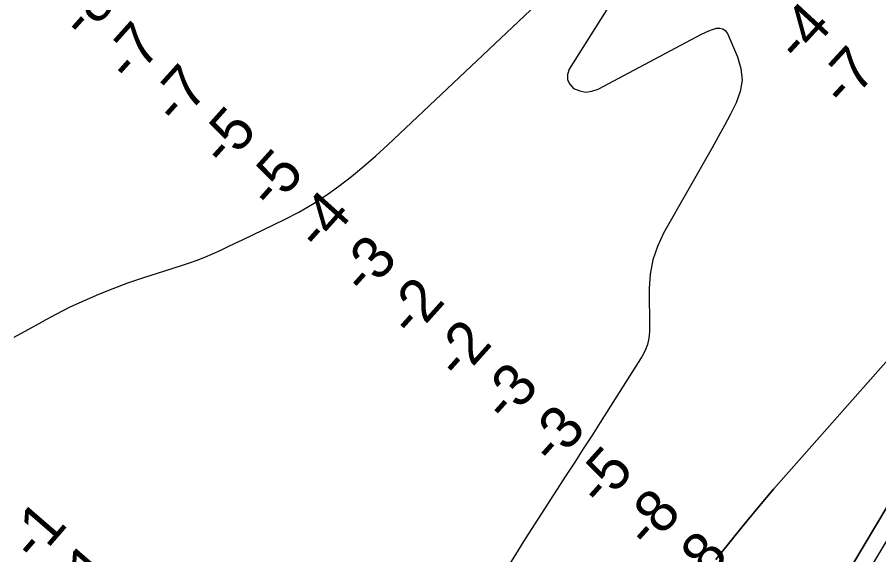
# Model space of a CAD drawing. Extents: x 3324104 to 3361979, y 612876 to 638273.
# Drawn here: x 3338795 to 3340154, y 623340 to 624187 of the extents above; entities that cross this region are included whole.
import ezdxf

# ---------------------------------------------------------------- set-up
doc = ezdxf.new("R2010")
doc.units = 0
for name, color, linetype in [('V-RIVR-EDGE', 7, 'Continuous'), ('V-RIVR-RANG', 7, 'Continuous'), ('V-TOPO-DPTH', 7, 'Continuous'), ('V-TOPO-MINR', 7, 'Continuous')]:
    doc.layers.add(name, color=color, linetype=linetype)

msp = doc.modelspace()

# ---------------------------------------------------------------- linework, layer by layer
at = {"layer": 'V-RIVR-EDGE'}
msp.add_spline([(3338849.5, 620833.7), (3338863.9, 620858.4), (3338873.2, 620877), (3338879.5, 620892.9), (3338887.7, 620911.1), (3338889.2, 620920.8), (3338889.3, 620930.9), (3338889.3, 620936.7), (3338892.8, 620944.8), (3338909.2, 620979.3), (3338928.6, 621017.7), (3338934.9, 621032.8), (3338933, 621036.3), (3338935.3, 621042.1), (3338955.2, 621075.8), (3338956.3, 621080), (3338951.3, 621082.4), (3338952.5, 621087.4), (3338954, 621094.8), (3338957.5, 621099.4), (3338963, 621104.8), (3338961.4, 621110.7), (3338960.7, 621117.6), (3338962.2, 621121.5), (3338980.9, 621151.3), (3338987.5, 621160.2), (3338994.6, 621173), (3339001.6, 621180.4), (3339008.6, 621185.8), (3339012.8, 621191.6), (3339013.6, 621197), (3339013.2, 621200.9), (3339009.8, 621206.7), (3339008.2, 621211.8), (3339009, 621213.7), (3339012.5, 621216.8), (3339014.8, 621221.1), (3339014.9, 621226.5), (3339018.4, 621227.2), (3339028, 621227.6), (3339031.2, 621232.3), (3339035.1, 621243.9), (3339039.8, 621256.3), (3339042.9, 621268.7), (3339045.6, 621270.2), (3339049.9, 621273.7), (3339052.6, 621276.8), (3339055.3, 621283.8), (3339058.5, 621297.7), (3339063.5, 621308.2), (3339066.3, 621319), (3339072.9, 621338), (3339074.5, 621340.7), (3339071.8, 621346.2), (3339071.4, 621350.8), (3339070.6, 621355.9), (3339070.6, 621360.9), (3339074.6, 621374.9), (3339080, 621383.4), (3339091.3, 621402), (3339101.8, 621418.6), (3339106.9, 621432.2), (3339108.9, 621448.5), (3339114.7, 621460.9), (3339121.7, 621472.9), (3339138.1, 621494.5), (3339146.6, 621512.7), (3339150.9, 621515.8), (3339154, 621517), (3339157.5, 621520.5), (3339162.2, 621524.7), (3339162.6, 621530.9), (3339163, 621535.2), (3339166.5, 621539.4), (3339173.9, 621548.4), (3339187.9, 621560), (3339202.3, 621575.4), (3339208.5, 621582), (3339220.9, 621601.4), (3339227.2, 621611.8), (3339228.3, 621618.4), (3339232.6, 621620.7), (3339234.6, 621627.7), (3339234.6, 621632.4), (3339233.8, 621643.2), (3339233.9, 621652.9), (3339235, 621660.7), (3339237.8, 621668.8), (3339245.6, 621681.6), (3339256.4, 621692), (3339259.6, 621702.1), (3339260.4, 621709.5), (3339267.8, 621721.9), (3339275.9, 621735.4), (3339287.3, 621761), (3339293.1, 621772.6), (3339304, 621793.5), (3339318, 621822.9), (3339329.7, 621836.9), (3339335.2, 621843.1), (3339330.5, 621848.9), (3339330.5, 621851.6), (3339333.3, 621855.9), (3339336.4, 621859.7), (3339342.2, 621865.5), (3339347.6, 621869.8), (3339357, 621888), (3339376.1, 621923.6), (3339382.7, 621941.8), (3339386.6, 621950.8), (3339393.2, 621962.8), (3339404.5, 621981.7), (3339427.1, 622013.9), (3339446.2, 622044.5), (3339464.1, 622073.5), (3339479.3, 622102.9), (3339498.8, 622140.9), (3339514.4, 622174.6), (3339531.9, 622205.2), (3339537.7, 622216), (3339537.7, 622219.9), (3339534.7, 622225.7), (3339534.7, 622228.8), (3339534.7, 622231.9), (3339539.7, 622235), (3339547.5, 622242.8), (3339556.8, 622254), (3339556.8, 622259.8), (3339555.7, 622266.4), (3339558.4, 622271.4), (3339563.9, 622273.7), (3339568.6, 622287.7), (3339574, 622293.9), (3339576.3, 622298.5), (3339576.4, 622305.1), (3339577.9, 622309.8), (3339583.4, 622315.6), (3339592.7, 622321.8), (3339605.1, 622339.6), (3339611, 622347.3), (3339621.1, 622355.4), (3339623.8, 622361.6), (3339624.2, 622367.4), (3339624.6, 622374.8), (3339628.1, 622381.4), (3339634.7, 622394.2), (3339652.6, 622417.8), (3339667, 622436.8), (3339680.3, 622456.9), (3339694.3, 622479), (3339705.2, 622499.1), (3339708.7, 622510.7), (3339714.6, 622523.5), (3339723.1, 622538.6), (3339729.4, 622550.2), (3339737.9, 622567.3), (3339738.7, 622571.9), (3339742.2, 622573.5), (3339746.9, 622573.8), (3339748.4, 622577.7), (3339749.2, 622585.1), (3339752, 622591.3), (3339757.8, 622596.7), (3339769.1, 622612.6), (3339778.4, 622620.3), (3339791.2, 622628), (3339795.5, 622636.5), (3339804.1, 622654), (3339820.4, 622682.2), (3339834.5, 622707.8), (3339891.3, 622796.9), (3339910, 622829.4), (3339944.6, 622882.4), (3339978.1, 622936.2), (3339998.7, 622964.9), (3340017.1, 622997.8), (3340021, 623017.2), (3340025.7, 623025.3), (3340038.9, 623040.4), (3340052.9, 623059.4), (3340070.8, 623091.9), (3340085.6, 623112.8), (3340108.6, 623149.2), (3340144.4, 623201.5), (3340174, 623254.2), (3340198.1, 623280.1), (3340221.4, 623307.2), (3340237, 623327.3), (3340244.4, 623342), (3340256.8, 623363.3), (3340272.8, 623384.6), (3340289.1, 623408.2), (3340302.8, 623428.7), (3340311.7, 623438.8), (3340319.5, 623450.4), (3340319.5, 623457.8), (3340325, 623465.9), (3340333.5, 623476.7), (3340341.3, 623483.3), (3340352.2, 623496.5), (3340367.4, 623520.1), (3340394.2, 623560), (3340400.1, 623574.3), (3340403.2, 623588.6), (3340409.1, 623600.7), (3340420.7, 623609.9), (3340437, 623624.6), (3340446.4, 623639.7), (3340451.1, 623650.6), (3340458.1, 623662.2), (3340477.1, 623683.9), (3340488, 623697)], degree=3, dxfattribs=at)
at = {"layer": 'V-TOPO-DPTH'}
for points in [[(3339896.4, 623332.9), (3339903.2, 623341.2), (3339938.3, 623384.4), (3339962.8, 623414.2), (3339987.5, 623443.7), (3340345.6, 623847.9), (3340365.7, 623866.5), (3340387.4, 623883.3), (3340410, 623898.9), (3340464.3, 623932.8), (3340471.7, 623933.2), (3340476.9, 623931.4), (3340478.7, 623926.3), (3340478.3, 623918.9), (3340474.1, 623912.1), (3340464.4, 623897), (3340454.5, 623882.1), (3340444.2, 623867.4), (3340433.7, 623852.9), (3340423, 623838.5), (3340412.3, 623824), (3340401.8, 623809.5), (3340077.1, 623265.5)], [(3340077.1, 623265.5), (3340401.8, 623809.5), (3340412.3, 623824), (3340423, 623838.5), (3340433.7, 623852.9), (3340444.2, 623867.4), (3340454.5, 623882.1), (3340464.4, 623897), (3340474.1, 623912.1), (3340478.3, 623918.9), (3340478.7, 623926.3), (3340476.9, 623931.4), (3340471.7, 623933.2), (3340464.3, 623932.8), (3340410, 623898.9), (3340387.4, 623883.3), (3340365.7, 623866.5), (3340345.6, 623847.9), (3339987.5, 623443.7), (3339962.8, 623414.2), (3339938.3, 623384.4), (3339903.2, 623341.2), (3339896.4, 623332.9)]]:
    msp.add_lwpolyline(points, dxfattribs=at)
at = {"layer": 'V-TOPO-MINR'}
for points in [[(3338789.5, 623683), (3338811.6, 623695.1), (3338833.6, 623707.4), (3338834.3, 623707.8), (3338856.1, 623719.6), (3338878, 623730.7), (3338900.4, 623741.1), (3338923.1, 623750.9), (3338946.1, 623759.9), (3338969.2, 623768.6), (3338992.5, 623776.6), (3339016, 623784.2), (3339053.8, 623796), (3339066.2, 623800.1), (3339078.5, 623804.5), (3339090.6, 623809.4), (3339102.6, 623814.5), (3339114.5, 623820), (3339126.4, 623825.5), (3339138.2, 623831.1), (3339150, 623836.7), (3339216.3, 623868.7), (3339238.6, 623880.3), (3339260.5, 623892.7), (3339281.5, 623906.5), (3339302, 623921.1), (3339321.9, 623936.6), (3339341.4, 623952.6), (3339360.4, 623969.1), (3339379, 623986.1), (3339791.6, 624375.5)], [(3339820, 624350.9), (3339665.2, 624105.6), (3339662.5, 624097), (3339662.3, 624088.9), (3339666, 624081.7), (3339672.2, 624075.2), (3339681.8, 624071.3), (3339691.4, 624069.4), (3339701.1, 624070.7), (3339710.8, 624074), (3339874.1, 624160.8), (3339879.7, 624163.6), (3339885.5, 624166.1), (3339891.4, 624168.3), (3339897.4, 624170.2), (3339902.8, 624170.4), (3339907.6, 624169.3), (3339911.5, 624166.3), (3339914.7, 624162), (3339930.9, 624124.8), (3339936.1, 624106.5), (3339938, 624088.3), (3339935, 624070.2), (3339928.7, 624052.3), (3339919.5, 624034.4), (3339910, 624016.7), (3339900.4, 623999.1), (3339890.6, 623981.6), (3339814.1, 623847), (3339804.4, 623826.2), (3339797, 623804.8), (3339793, 623782.5), (3339791.4, 623759.6), (3339791.6, 623733.8), (3339791.7, 623723.3), (3339791.7, 623712.8), (3339791.7, 623702.3), (3339791.7, 623691.8), (3339790.8, 623681.6), (3339788.8, 623671.7), (3339785.1, 623662.2), (3339780.4, 623653.1), (3339713.9, 623548.4), (3339700.7, 623527.6), (3339687.4, 623506.9), (3339674.1, 623486.2), (3339660.7, 623465.5), (3339595.7, 623365.4), (3339559.9, 623307.4)], [(3340077.1, 623265.5), (3340401.8, 623809.5), (3340412.3, 623824), (3340423, 623838.5), (3340433.7, 623852.9), (3340444.2, 623867.4), (3340454.5, 623882.1), (3340464.4, 623897), (3340474.1, 623912.1), (3340478.3, 623918.9), (3340478.7, 623926.3), (3340476.9, 623931.4), (3340471.7, 623933.2), (3340464.3, 623932.8), (3340410, 623898.9), (3340387.4, 623883.3), (3340365.7, 623866.5), (3340345.6, 623847.9), (3339987.5, 623443.7), (3339962.8, 623414.2), (3339938.3, 623384.4), (3339903.2, 623341.2), (3339896.4, 623332.9)], [(3340107.1, 623263.2), (3340432.9, 623805.1)]]:
    msp.add_lwpolyline(points, dxfattribs=at)

# ---------------------------------------------------------------- texts
at = {"layer": 'V-RIVR-RANG'}
for s, rotation, p in [('-8', 48.1109, (3338899.8, 624149.9)), ('-4', 47.3354, (3340028.3, 624113)), ('-7', 48.1109, (3338972.7, 624081.3)), ('-7', 47.3354, (3340099.7, 624042.9)), ('-7', 48.1109, (3339047, 624014.4)), ('-5', 48.1109, (3339121.9, 623948.2)), ('-5', 48.1109, (3339196.2, 623881.3)), ('-4', 48.1109, (3339271.7, 623815.7)), ('-3', 48.1109, (3339343.7, 623746.2)), ('-2', 48.1109, (3339418.3, 623679.6)), ('-2', 48.1109, (3339492.6, 623612.7)), ('-3', 48.1109, (3339566.6, 623545.3)), ('-3', 48.1109, (3339640.8, 623478.4)), ('-5', 48.1109, (3339716.2, 623412.6)), ('-8', 48.1109, (3339791.2, 623346.4)), ('-1', 49.2162, (3338823.1, 623326.2)), ('-8', 48.1109, (3339865.4, 623279.5)), ('-1', 49.2162, (3338898.7, 623260.7))]:
    msp.add_text(s, height=67, rotation=rotation, dxfattribs=at).set_placement(p)

doc.saveas('drawing.dxf')
